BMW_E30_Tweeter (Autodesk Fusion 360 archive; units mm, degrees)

design "Pieza rara - Revised Sizes" references "Pieza rara - slopes edition"
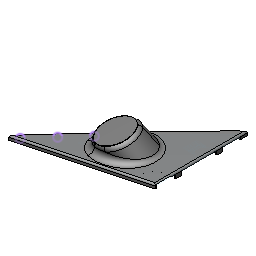
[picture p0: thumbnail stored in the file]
sketch "Sketch1" plane through (0, 0, 0) normal (0, 1, 0) x axis (1, 0, 0)
  line L1 (0, 113) -> (0, 0)
  line L2 (0, 0) -> (0, 113)
  line L3 (-141.545, -37.9726) -> (0, 0)
  point P1 (0, 0)
  point P2 (0, 0)
  point P4 (0, 0)
  point P5 (0, 0)
  point P3 (0, 113)
  point P6 (-141.545, -37.9726)
  vertical L1
  coincident P1 P2
  coincident P1 P4
  coincident P1 P5
  dimension "d1" distance P2 P3 = 113
  dimension "d2" distance P5 P6 = 146.55
sketch "Sketch2" plane through (0, 0, 0) normal (0, 1, 0) x axis (-1, 0, 0)
  curve K1 (0, -113) -> (141.545, 37.9726)
  line L1 (0, 0) -> (0, -113)
  line L2 (141.545, 37.9726) -> (0, 0)
  point P3 (141.545, 37.9726)
  point P5 (141.545, 37.9726)
  point P4 (0, -113)
  point P6 (0, -113)
  point P1 (0, 0)
  point P7 (0, 0)
  point P2 (55.2155, -56.5)
  coincident P3 P5
  coincident P4 P6
  coincident P1 P7
  dimension "d3" distance P1 P2 = 79
extrude "Extrude1" new body sketch "Sketch2" along normal blind 5
shell "Shell1" innerThickness 2
sketch "Sketch3" plane through (0, 3, 0) normal (0, -1, 0) x axis (1, 0, 0)
  line L1 (-2, -1.5342) -> (-2, -108.2224)
  line L2 (-135.5783, 34.3012) -> (-2, -1.5342)
  curve K1 (-2, -108.2224) -> (-135.5783, 34.3012)
  curve K2 (0, -113) -> (-141.545, 37.9726)
  line L3 (-21.3711, -13.7183) -> (-14.6264, -21.1013)
  line L4 (-54.4946, -57.5228) -> (-61.2393, -50.1398)
  line L5 (-41.3052, -31.929) -> (-34.5605, -39.312)
  arc A1 centre (-41.3052, -31.929) radius 27 clockwise from (-61.2393, -50.1398) to (-21.3711, -13.7183)
  arc A2 centre (-34.5605, -39.312) radius 27 clockwise from (-14.6264, -21.1013) to (-54.4946, -57.5228)
  point P7 (-56.867, -51.8313)
  point P15 (-34.5605, -39.312)
  point P17 (-34.5605, -39.312)
  point P16 (-41.3052, -31.929)
  point P18 (-41.3052, -31.929)
  point P9 (-16.9988, -15.4098)
  coincident K1 P7
  tangent L3 A1
  tangent A1 L4
  parallel L3 L4
  tangent L4 A2
  tangent L3 A2
  coincident P15 P17
  coincident P16 P18
  dimension "d7" distance P7 P9 = 54
sketch "Sketch4" plane through (0, 0, 0) normal (0, 0, 1) x axis (1, 0, 0)
  line L1 (-41.3052, 0) -> (-34.5605, 0)
  line L2 (-37.9329, 0) -> (-52.1255, 21.0623)
  circle C1 centre (-52.1255, 21.0623) radius 21.25
  point P2 (-52.1255, 21.0623)
  point P5 (-52.1255, 21.0623)
  point P7 (-52.1255, 21.0623)
  point P9 (-37.9329, 0)
  point P10 (-52.1255, 21.0623)
  point P11 (-37.9329, 0)
  point P12 (-52.1255, 21.0623)
  coincident P2 P5
  coincident P5 P7
  midpoint L1 P9
  coincident P7 P10
  coincident P9 P11
  coincident P5 P12
  dimension "d10" diameter C1 = 42.5
external_derived "ExternalDerived1"
move "Move1"
move "Move2"
move "Move3"
combine "Combine1"
offset_faces "OffsetFaces1" distance 0.066
delete_face "DeleteFace1"
sketch "Sketch5" plane through (0, 3, 0) normal (0, -1, 0) x axis (1, 0, 0)
  curve K1 (-34.855, -41.4726) -> (-64.6786, -43.3994)
  curve K2 (-2.066, -108.0644) -> (-64.6786, -43.3994)
  line L1 (-2.066, -1.5848) -> (-2.066, -108.0644)
  line L2 (-135.3812, 34.18) -> (-2.066, -1.5848)
  curve K3 (-69.9493, -37.7406) -> (-135.3812, 34.18)
  curve K4 (-69.9493, -37.7406) -> (-34.855, -41.4726)
  line L3 (-95.1633, -10.3455) -> (-135.3812, 34.18)
  line L4 (-89.7132, -5.4227) -> (-95.1633, -10.3455)
  line L5 (-93.1705, -1.5951) -> (-89.7132, -5.4227)
  line L6 (-92.5002, -2.3372) -> (-93.1705, -1.5951)
  line L7 (-92.5002, -2.3372) -> (-93.1705, -1.5951)
  line L8 (-88.7898, 1.0143) -> (-92.5002, -2.3372)
  line L9 (-89.4601, 1.7564) -> (-88.7898, 1.0143)
  line L10 (-93.1705, -1.5951) -> (-89.4601, 1.7564)
  line L11 (-91.6863, -0.2545) -> (-93.1705, -1.5951)
  line L12 (-93.0269, 1.2296) -> (-91.6863, -0.2545)
  line L13 (-92.2849, 1.8999) -> (-93.0269, 1.2296)
  line L14 (-90.9443, 0.4158) -> (-92.2849, 1.8999)
  line L15 (-92.2849, 1.8999) -> (-93.0269, 1.2296)
  line L16 (-88.9334, -1.8105) -> (-92.2849, 1.8999)
  line L17 (-89.6754, -2.4808) -> (-88.9334, -1.8105)
  line L18 (-93.0269, 1.2296) -> (-89.6754, -2.4808)
  line L19 (-2.066, -83.0644) -> (-2.066, -108.0644)
  line L20 (-10.066, -83.0644) -> (-2.066, -83.0644)
  line L21 (-10.066, -84.0644) -> (-10.066, -83.0644)
  line L22 (-10.066, -84.0644) -> (-10.066, -83.0644)
  line L23 (-15.066, -84.0644) -> (-10.066, -84.0644)
  line L24 (-15.066, -83.0644) -> (-15.066, -84.0644)
  line L25 (-10.066, -83.0644) -> (-15.066, -83.0644)
  line L26 (-12.066, -83.0644) -> (-10.066, -83.0644)
  line L27 (-12.066, -81.0644) -> (-12.066, -83.0644)
  line L28 (-13.066, -81.0644) -> (-12.066, -81.0644)
  line L29 (-13.066, -86.0644) -> (-13.066, -81.0644)
  line L30 (-12.066, -86.0644) -> (-13.066, -86.0644)
  line L31 (-12.066, -81.0644) -> (-12.066, -86.0644)
  point P6 (-135.3812, 34.18)
  point P8 (-135.3812, 34.18)
  point P9 (-135.3812, 34.18)
  point P10 (-95.1633, -10.3455)
  point P16 (-91.6863, -0.2545)
  point P19 (-90.9443, 0.4158)
  point P4 (-2.066, -108.0644)
  point P22 (-2.066, -108.0644)
  point P23 (-2.066, -108.0644)
  point P24 (-2.066, -83.0644)
  point P12 (-93.1705, -1.5951)
  point P15 (-89.4601, 1.7564)
  point P17 (-93.0269, 1.2296)
  point P18 (-92.2849, 1.8999)
  point P21 (-89.6754, -2.4808)
  point P25 (-10.066, -83.0644)
  point P26 (-10.066, -84.0644)
  point P28 (-15.066, -83.0644)
  point P29 (-12.066, -83.0644)
  point P30 (-12.066, -81.0644)
  point P31 (-13.066, -81.0644)
  point P33 (-12.066, -86.0644)
  coincident P6 P8
  coincident P8 P9
  coincident K3 P10
  perpendicular L3 L4
  perpendicular L4 L5
  perpendicular L4 L6
  perpendicular L7 L8
  parallel L7 L9
  parallel L8 L10
  coincident L10 P16
  perpendicular L11 L12
  perpendicular L12 L13
  coincident L10 P19
  perpendicular L10 L14
  perpendicular L15 L16
  parallel L15 L17
  parallel L16 L18
  coincident P4 P22
  coincident P22 P23
  coincident L1 P24
  perpendicular L19 L20
  perpendicular L20 L21
  perpendicular L22 L23
  parallel L22 L24
  parallel L23 L25
  perpendicular L22 L26
  perpendicular L26 L27
  perpendicular L28 L29
  parallel L28 L30
  parallel L29 L31
  perpendicular L27 L28
  dimension "d24" distance P9 P10 = 60
  dimension "d28" distance P12 P15 = 5
  dimension "d29" distance P12 P16 = 2
  dimension "d30" distance P16 P17 = 2
  dimension "d31" distance P17 P18 = 1
  dimension "d32" distance P17 P21 = 5
  dimension "d41" distance P25 P26 = 1
  dimension "d42" distance P25 P28 = 5
  dimension "d43" distance P25 P29 = 2
  dimension "d44" distance P29 P30 = 2
  dimension "d45" distance P30 P31 = 1
  dimension "d46" distance P30 P33 = 5
extrude "Extrude4" add sketch "Sketch5" profile of L5 L6 L7 L8 L9 L10 L11 L12 L13 L14 L15 L16 L17 L18 along normal blind 12
fillet "Fillet5" radius 2
fillet "Fillet6" radius 7
extrude "Extrude5" add sketch "Sketch5" profile of L21 L22 L23 L24 L25 L26 L27 L28 L29 L30 L31 along normal blind 12
fillet "Fillet7" radius 2
fillet "Fillet8" radius 2
sketch "Sketch6" plane through (0, 0, 0) normal (0, -1, 0) x axis (1, 0, 0)
  line L1 (0, 0) -> (0, -113)
  line L2 (-141.545, 37.9726) -> (0, 0)
  curve K1 (0, -113) -> (-141.545, 37.9726)
  curve K2 (-62.4775, -45.7545) -> (-68.7755, -39.0032)
  curve K3 (-68.7755, -39.0032) -> (-135.3812, 34.18)
  line L3 (-2.066, -1.5848) -> (-135.3812, 34.18)
  line L4 (-2.066, -108.0644) -> (-2.066, -1.5848)
  curve K4 (-2.066, -108.0644) -> (-62.4775, -45.7545)
  line L5 (-138.2134, 34.2442) -> (-141.545, 37.9726)
  line L6 (-134.877, 30.5202) -> (-138.2134, 34.2442)
  curve K5 (-139.1097, 35.2486) -> (-73.8429, -36.5831)
  line L7 (-114.8104, 8.2179) -> (-134.8763, 30.5194)
  line L8 (-113.1141, 6.342) -> (-114.8104, 8.2179)
  line L9 (-134.877, 30.5202) -> (-113.1141, 6.342)
  line L10 (-134.8763, 30.5194) -> (-134.877, 30.5202)
  line L11 (-134.8763, 30.5194) -> (-134.877, 30.5202)
  line L12 (-113.1141, 6.342) -> (-114.8104, 8.2179)
  line L13 (-134.877, 30.5202) -> (-113.1141, 6.342)
  line L14 (-134.877, 30.5202) -> (-134.8763, 30.5194)
  line L15 (-114.8104, 8.2179) -> (-134.8763, 30.5194)
  point P4 (-141.545, 37.9726)
  point P10 (-141.545, 37.9726)
  point P13 (-134.877, 30.5202)
  point P16 (-134.8763, 30.5194)
  point P17 (-114.8104, 8.2179)
  point P18 (-113.1141, 6.342)
  point P12 (-138.2134, 34.2442)
  coincident P4 P10
  coincident K1 P13
  coincident K5 P16
  coincident K5 P17
  coincident K1 P18
  dimension "d57" distance P10 P12 = 5
  dimension "d58" distance P12 P13 = 5
  dimension "d59" distance P16 P17 = 30
split_face "SplitFace1"
split_face "SplitFace2"
delete_face "DeleteFace4"
sketch "Sketch7" plane through (0, 0, 0) normal (0, -1, 0) x axis (1, 0, 0)
  curve K1 (-68.7755, -39.0032) -> (-135.3812, 34.18)
  line L1 (-133.3529, 31.9152) -> (-134.877, 30.5202)
  line L2 (-111.5901, 7.7369) -> (-113.1141, 6.342)
  line L3 (-133.3529, 31.9152) -> (-134.877, 30.5202)
  line L4 (-111.3903, 7.9198) -> (-133.3529, 31.9152)
  line L5 (-112.9143, 6.5249) -> (-111.3903, 7.9198)
  line L6 (-134.877, 30.5202) -> (-112.9143, 6.5249)
  point P2 (-134.877, 30.5202)
  point P5 (-134.877, 30.5202)
  point P6 (-133.3529, 31.9152)
  point P7 (-113.1141, 6.342)
  point P8 (-113.1141, 6.342)
  point P9 (-111.5901, 7.7369)
  point P10 (-134.877, 30.5202)
  coincident P2 P5
  coincident K1 P6
  coincident P7 P8
  coincident K1 P9
  parallel L1 L2
  perpendicular L3 L4
  parallel L3 L5
  parallel L4 L6
  parallel L1 L3
  coincident P2 P10
split_face "SplitFace3"
extrude "Extrude6" cut sketch "Sketch7" profile of K1 L1 L2 L3 L5 L6 against normal blind 3
delete_face "DeleteFace5"
step "RemoveFaces1"
step "RemoveFaces2"
chamfer "Chamfer1" distance 3
sketch "Sketch8" plane through (-52.1255, 21.0623, -25.2438) normal (-0.1729, 0.9763, 0.1303) x axis (0, -0.1323, 0.9912)
  circle C1 centre (2.2976, -2.1686) radius 23.5648
scale "Scale1" ScaleFactor 1.1561
sketch "Sketch9" plane through (0, 0, 0) normal (1, 0, 0) x axis (0, 0, -1)
  line L1 (113, 0) -> (113, 3)
  line L2 (0, 3) -> (113, 3)
  line L3 (0, 0) -> (0, 3)
  line L4 (113, 0) -> (0, 0)
  line L5 (104, 0) -> (113, 0)
  line L6 (104, 3) -> (104, 0)
  line L7 (104, 3) -> (104, 0)
  line L8 (82.89, 3) -> (104, 3)
  line L9 (82.89, 0) -> (82.89, 3)
  line L10 (104, 0) -> (82.89, 0)
  line L11 (82.89, 3) -> (82.89, 0)
  line L12 (75.69, 3) -> (82.89, 3)
  line L13 (75.69, 0) -> (75.69, 3)
  line L14 (82.89, 0) -> (75.69, 0)
  line L15 (75.69, 3) -> (75.69, 0)
  line L16 (32.29, 3) -> (75.69, 3)
  line L17 (32.29, 0) -> (32.29, 3)
  line L18 (75.69, 0) -> (32.29, 0)
  line L19 (32.29, 0) -> (32.29, 3)
  line L20 (25.09, 0) -> (32.29, 0)
  line L21 (25.09, 3) -> (25.09, 0)
  line L22 (32.29, 3) -> (25.09, 3)
  line L23 (25.09, 3) -> (25.09, 0)
  line L24 (0, 3) -> (25.09, 3)
  line L25 (0, 0) -> (0, 3)
  line L26 (25.09, 0) -> (0, 0)
  point P3 (113, 0)
  point P6 (113, 0)
  point P7 (104, 0)
  point P8 (104, 3)
  point P10 (82.89, 0)
  point P12 (75.69, 0)
  point P14 (32.29, 0)
  point P13 (32.29, 3)
  point P16 (25.09, 3)
  coincident P3 P6
  coincident L4 P7
  coincident L2 P8
  perpendicular L2 L6
  perpendicular L7 L8
  parallel L7 L9
  parallel L8 L10
  perpendicular L11 L12
  parallel L11 L13
  parallel L12 L14
  perpendicular L15 L16
  parallel L15 L17
  parallel L16 L18
  perpendicular L19 L20
  parallel L19 L21
  parallel L20 L22
  perpendicular L23 L24
  parallel L23 L25
  parallel L24 L26
  dimension "d67" distance P6 P7 = 9
  dimension "d68" distance P7 P10 = 21.11
  dimension "d69" distance P10 P12 = 7.2
  dimension "d70" distance P12 P14 = 43.4
  dimension "d71" distance P13 P16 = 7.2
sketch "Sketch10" plane through (0, 0, 0) normal (0, -1, 0) x axis (1, 0, 0)
  line L1 (-111.1011, 4.1176) -> (-109.577, 5.5126)
  curve K1 (-111.1011, 4.1176) -> (0, -113)
  line L2 (0, 0) -> (0, -113)
  line L3 (-141.545, 37.9726) -> (0, 0)
  curve K2 (-141.545, 37.9726) -> (-134.877, 30.5202)
  line L4 (-133.3529, 31.9152) -> (-134.877, 30.5202)
  curve K3 (-133.3529, 31.9152) -> (-135.3812, 34.18)
  line L5 (-2.066, -1.5848) -> (-135.3812, 34.18)
  line L6 (-2.066, -108.0644) -> (-2.066, -1.5848)
  curve K4 (-2.066, -108.0644) -> (-109.577, 5.5126)
  line L7 (0, -2.1391) -> (-2.066, -1.5848)
  line L8 (0, 0) -> (0, -25.09)
  line L9 (0, -2.1391) -> (0, -2.1391)
  point P10 (-2.066, -1.5848)
  point P12 (-2.066, -1.5848)
  point P13 (0, -2.1391)
  point P16 (0, -2.1391)
  coincident P10 P12
  coincident L2 P13
  parallel L5 L7
  coincident L8 P16
sketch "Sketch11" plane through (0, 0, 0) normal (1, 0, 0) x axis (0, 0, -1)
  line L1 (25.09, 0) -> (25.09, 3)
  line L2 (2.1391, 0) -> (25.09, 0)
  line L3 (2.1391, 3) -> (2.1391, 0)
  line L4 (25.09, 3) -> (2.1391, 3)
  point P3 (25.09, 0)
  point P7 (25.09, 0)
  point P2 (25.09, 3)
  point P6 (25.09, 3)
  perpendicular L1 L2
  parallel L1 L3
  parallel L2 L4
  coincident P3 P7
  coincident P2 P6
extrude "Extrude7" cut sketch "Sketch9" profile of L2 L4 L13 L15 L16 L17 L18 L19 against normal blind 4
extrude "Extrude8" cut sketch "Sketch9" profile of L2 L4 L6 L7 L8 L9 L10 L11 against normal blind 4
extrude "Extrude9" cut sketch "Sketch11" against normal blind 3
delete_face "DeleteFace6"
chamfer "Chamfer2" distance 0.8 distance 3
chamfer "Chamfer3" distance 0.8 distance 3
chamfer "Chamfer4" distance 0.8 distance 3
extrude "Extrude10" add of existing geometry blind 2
sketch "Sketch12" plane through (-0.5353, 0, -1.9954) normal (-0.2591, 0, -0.9658) x axis (-0.9658, 0, 0.2591)
  line L1 (-0.5543, 3) -> (139.614, 3)
  line L2 (-0.5543, 0) -> (-0.5543, 3)
  line L3 (139.614, 0) -> (-0.5543, 0)
  line L4 (139.614, 0) -> (139.614, 3)
sketch "Sketch13" plane through (-0.5353, 0, -1.9954) normal (-0.2591, 0, -0.9658) x axis (-0.9658, 0, 0.2591)
  line L1 (-0.5543, 3) -> (139.614, 3)
  line L2 (-0.5543, 0) -> (-0.5543, 3)
  line L3 (139.614, 0) -> (-0.5543, 0)
  line L4 (139.614, 0) -> (139.614, 3)
  line L5 (78.3765, 3) -> (78.3765, 0)
  line L6 (75.3765, 3) -> (78.3765, 3)
  line L7 (75.3765, 0) -> (75.3765, 3)
  line L8 (78.3765, 0) -> (75.3765, 0)
  line L9 (75.3765, 3) -> (78.3765, 3)
  line L10 (75.3765, 1) -> (75.3765, 3)
  line L11 (78.3765, 1) -> (75.3765, 1)
  line L12 (78.3765, 3) -> (78.3765, 1)
  point P7 (78.3765, 3)
  point P6 (78.3765, 0)
  point P9 (75.3765, 0)
  point P11 (78.3765, 1)
  perpendicular L5 L6
  parallel L5 L7
  parallel L6 L8
  coincident L1 P7
  perpendicular L1 L5
  coincident L3 P6
  perpendicular L9 L10
  parallel L9 L11
  parallel L10 L12
  dimension "d86" distance P6 P9 = 3
  dimension "d87" distance P7 P11 = 2
extrude "Extrude11" add sketch "Sketch13" profile of L1 L5 L6 L7 L9 L10 L11 L12 along normal blind 41.5
offset_faces "OffsetFaces5" distance -1
sketch "Sketch14" plane through (0, 3, 0) normal (0, -1, 0) x axis (1, 0, 0)
  line L1 (-76.8828, 4.3204) -> (-73.3376, 17.5354)
  curve K1 (-76.8828, 4.3204) -> (-62.2677, 9.2949)
  curve K2 (-62.2677, 9.2949) -> (-56.8017, -51.8044)
  curve K3 (-2.066, -108.0644) -> (-56.8017, -51.8044)
  line L2 (-2.066, -104) -> (-2.066, -108.0644)
  line L3 (0, -104) -> (-2.066, -104)
  line L4 (0, -82.89) -> (0, -104)
  line L5 (-2.066, -82.89) -> (0, -82.89)
  line L6 (-2.066, -75.69) -> (-2.066, -82.89)
  line L7 (0, -75.69) -> (-2.066, -75.69)
  line L8 (0, -32.29) -> (0, -75.69)
  line L9 (-2.066, -32.29) -> (0, -32.29)
  line L10 (-2.066, -25.09) -> (-2.066, -32.29)
  line L11 (0, -25.09) -> (-2.066, -25.09)
  line L12 (0, -2.1391) -> (0, -25.09)
  line L13 (-73.3376, 17.5354) -> (0, -2.1391)
  line L14 (-15.066, -84.0644) -> (-13.066, -84.0644)
  line L15 (-15.066, -83.0644) -> (-15.066, -84.0644)
  line L16 (-13.066, -83.0644) -> (-15.066, -83.0644)
  line L17 (-13.066, -81.0644) -> (-13.066, -83.0644)
  line L18 (-12.066, -81.0644) -> (-13.066, -81.0644)
  line L19 (-12.066, -83.0644) -> (-12.066, -81.0644)
  line L20 (-10.066, -83.0644) -> (-12.066, -83.0644)
  line L21 (-10.066, -84.0644) -> (-10.066, -83.0644)
  line L22 (-12.066, -84.0644) -> (-10.066, -84.0644)
  line L23 (-12.066, -86.0644) -> (-12.066, -84.0644)
  line L24 (-13.066, -86.0644) -> (-12.066, -86.0644)
  line L25 (-13.066, -84.0644) -> (-13.066, -86.0644)
sketch "Sketch15" plane through (0, 0, 0) normal (0, 1, 0) x axis (1, 0, 0)
  line L1 (0.2646, -423.3333) -> (0.2646, -211.799)
  line L2 (135.0698, -423.3333) -> (0.2646, -423.3333)
  line L3 (269.875, -423.3333) -> (135.0698, -423.3333)
  line L4 (269.875, -211.799) -> (269.875, -423.3333)
  line L5 (269.875, -0.2646) -> (269.875, -211.799)
  line L6 (135.0698, -0.2646) -> (269.875, -0.2646)
  line L7 (0.2646, -0.2646) -> (135.0698, -0.2646)
  line L8 (0.2646, -211.799) -> (0.2646, -0.2646)
  line L9 (76.7292, -29.6333) -> (76.7292, -19.7115)
  line L10 (67.601, -29.6333) -> (76.7292, -29.6333)
  line L11 (58.4729, -29.6333) -> (67.601, -29.6333)
  line L12 (58.4729, -24.8708) -> (58.4729, -29.6333)
  line L13 (58.4729, -20.1083) -> (58.4729, -24.8708)
  line L14 (52.2552, -20.1083) -> (58.4729, -20.1083)
  line L15 (46.0375, -20.1083) -> (52.2552, -20.1083)
  line L16 (46.0375, -32.9406) -> (46.0375, -20.1083)
  line L17 (46.0375, -45.7729) -> (46.0375, -32.9406)
  line L18 (50.7471, -45.72) -> (46.0375, -45.7729)
  line L19 (55.4302, -45.6406) -> (50.7471, -45.72)
  line L20 (55.5096, -43.5769) -> (55.4302, -45.6406)
  line L21 (55.589, -41.5396) -> (55.5096, -43.5769)
  line L22 (61.9919, -41.5925) -> (55.589, -41.5396)
  line L23 (68.3948, -41.6719) -> (61.9919, -41.5925)
  line L24 (68.3948, -51.1969) -> (68.3948, -41.6719)
  line L25 (68.3948, -60.7219) -> (68.3948, -51.1969)
  line L26 (61.9919, -60.8012) -> (68.3948, -60.7219)
  line L27 (55.5625, -60.8542) -> (61.9919, -60.8012)
  line L28 (55.536, -60.2721) -> (55.5625, -60.8542)
  curve K1 (55.4831, -58.2083) -> (55.536, -60.2721)
  line L29 (55.4302, -56.7531) -> (55.4831, -58.2083)
  line L30 (50.7206, -56.6737) -> (55.4302, -56.7531)
  line L31 (46.0375, -56.6208) -> (50.7206, -56.6737)
  line L32 (46.0904, -70.829) -> (46.0375, -56.6208)
  line L33 (46.1698, -85.0635) -> (46.0904, -70.829)
  line L34 (52.2552, -85.0635) -> (46.1698, -85.0635)
  line L35 (58.3406, -85.0635) -> (52.2552, -85.0635)
  line L36 (58.42, -78.7665) -> (58.3406, -85.0635)
  line L37 (58.4729, -72.4958) -> (58.42, -78.7665)
  line L38 (67.3365, -72.4958) -> (58.4729, -72.4958)
  line L39 (76.2, -72.4958) -> (67.3365, -72.4958)
  line L40 (76.2, -83.8465) -> (76.2, -72.4958)
  curve K2 (75.8031, -95.3558) -> (76.2, -83.8465)
  curve K3 (16.0337, -95.3558) -> (75.8031, -95.3558)
  curve K4 (15.6104, -91.784) -> (16.0337, -95.3558)
  line L41 (15.6104, -88.3708) -> (15.6104, -91.784)
  line L42 (16.9333, -87.5242) -> (15.6104, -88.3708)
  line L43 (18.2563, -86.651) -> (16.9333, -87.5242)
  line L44 (18.2563, -52.6521) -> (18.2563, -86.651)
  line L45 (18.2563, -18.6531) -> (18.2563, -52.6521)
  line L46 (16.9333, -17.7271) -> (18.2563, -18.6531)
  line L47 (15.6369, -16.801) -> (16.9333, -17.7271)
  line L48 (15.6104, -13.4673) -> (15.6369, -16.801)
  curve K5 (15.7956, -9.9748) -> (15.6104, -13.4673)
  curve K6 (46.355, -9.7896) -> (15.7956, -9.9748)
  line L49 (76.7292, -9.7896) -> (46.355, -9.7896)
  line L50 (76.7292, -19.7115) -> (76.7292, -9.7896)
  curve K7 (128.9844, -29.2365) -> (124.2748, -16.0073)
  curve K8 (133.0325, -40.5606) -> (128.9844, -29.2365)
  curve K9 (134.8052, -44.3706) -> (133.0325, -40.5606)
  curve K10 (141.4198, -26.8817) -> (134.8052, -44.3706)
  line L51 (147.7698, -9.7896) -> (141.4198, -26.8817)
  line L52 (165.1529, -9.7896) -> (147.7698, -9.7896)
  line L53 (182.5625, -9.7896) -> (165.1529, -9.7896)
  line L54 (182.5625, -13.2821) -> (182.5625, -9.7896)
  line L55 (182.536, -16.801) -> (182.5625, -13.2821)
  line L56 (181.2396, -17.8065) -> (182.536, -16.801)
  line L57 (179.9167, -18.8119) -> (181.2396, -17.8065)
  line L58 (179.9431, -52.7315) -> (179.9167, -18.8119)
  line L59 (179.9431, -86.651) -> (179.9431, -52.7315)
  line L60 (181.1867, -87.4712) -> (179.9431, -86.651)
  line L61 (182.4302, -88.2915) -> (181.1867, -87.4712)
  line L62 (182.4302, -91.8369) -> (182.4302, -88.2915)
  line L63 (182.4302, -95.3823) -> (182.4302, -91.8369)
  line L64 (166.5552, -95.4617) -> (182.4302, -95.3823)
  curve K11 (150.0981, -95.3823) -> (166.5552, -95.4617)
  curve K12 (149.4896, -91.9956) -> (150.0981, -95.3823)
  curve K13 (149.7013, -88.4767) -> (149.4896, -91.9956)
  curve K14 (150.9448, -87.4448) -> (149.7013, -88.4767)
  curve K15 (152.1883, -86.3865) -> (150.9448, -87.4448)
  curve K16 (152.1619, -38.8938) -> (152.1883, -86.3865)
  curve K17 (151.6592, -39.8727) -> (152.1619, -38.8938)
  curve K18 (146.976, -54.901) -> (151.6592, -39.8727)
  curve K19 (141.8167, -71.3052) -> (146.976, -54.901)
  curve K20 (139.8852, -77.5229) -> (141.8167, -71.3052)
  curve K21 (137.0013, -86.651) -> (139.8852, -77.5229)
  line L65 (135.3344, -91.9427) -> (137.0013, -86.651)
  line L66 (130.175, -91.9427) -> (135.3344, -91.9427)
  line L67 (125.0421, -91.9427) -> (130.175, -91.9427)
  line L68 (123.534, -87.0479) -> (125.0421, -91.9427)
  curve K22 (118.7979, -71.3052) -> (123.534, -87.0479)
  curve K23 (109.2729, -39.4229) -> (118.7979, -71.3052)
  curve K24 (109.0348, -62.7592) -> (109.2729, -39.4229)
  curve K25 (109.4846, -86.8892) -> (109.0348, -62.7592)
  curve K26 (110.8075, -87.8417) -> (109.4846, -86.8892)
  line L69 (111.6542, -88.6619) -> (110.8075, -87.8417)
  line L70 (111.6542, -91.9427) -> (111.6542, -88.6619)
  curve K27 (111.0721, -95.3823) -> (111.6542, -91.9427)
  curve K28 (98.9542, -95.4617) -> (111.0721, -95.3823)
  line L71 (87.4448, -95.3823) -> (98.9542, -95.4617)
  line L72 (87.3654, -91.8104) -> (87.4448, -95.3823)
  line L73 (87.3125, -88.2385) -> (87.3654, -91.8104)
  line L74 (88.6354, -87.339) -> (87.3125, -88.2385)
  line L75 (89.9583, -86.4394) -> (88.6354, -87.339)
  line L76 (89.9583, -52.6256) -> (89.9583, -86.4394)
  line L77 (89.9583, -18.8383) -> (89.9583, -52.6256)
  line L78 (88.6354, -17.8594) -> (89.9583, -18.8383)
  line L79 (87.3125, -16.8804) -> (88.6354, -17.8594)
  line L80 (87.3125, -13.335) -> (87.3125, -16.8804)
  line L81 (87.3125, -9.7896) -> (87.3125, -13.335)
  line L82 (104.7221, -9.8425) -> (87.3125, -9.7896)
  line L83 (122.1052, -9.9219) -> (104.7221, -9.8425)
  line L84 (124.2748, -16.0073) -> (122.1052, -9.9219)
  curve K29 (253.5238, -19.8173) -> (253.4973, -9.8954)
  line L85 (253.4708, -29.6333) -> (253.5238, -19.8173)
  line L86 (244.3427, -29.6333) -> (253.4708, -29.6333)
  line L87 (235.2146, -29.6333) -> (244.3427, -29.6333)
  line L88 (235.2146, -24.8708) -> (235.2146, -29.6333)
  line L89 (235.2146, -20.1083) -> (235.2146, -24.8708)
  line L90 (228.9969, -20.1083) -> (235.2146, -20.1083)
  line L91 (222.7792, -20.1083) -> (228.9969, -20.1083)
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extrude "Extrude12" new body sketch "Sketch15" along normal blind 1
move "Move4"
move "Move5"
scale "Scale2" ScaleFactor 0.07
combine "Combine2"
move "Move6"
move "Move7"
extrude "Extrude13" add of existing geometry blind 1
combine "Combine3"
surface_patch "SurfacePatch1"
extrude "Extrude14" cut of existing geometry blind 1
hole "Hole1" HoleDepth 0.5 HoleDiameter 1 TipAngle 118
surface_delete_face "SurfaceDeleteFace1"
extrude "Extrude16" new body of existing geometry blind 1
combine "Combine4"
delete_face "DeleteFace7"
extrude "Extrude17" cut of existing geometry blind -1
fillet "Fillet10" radius 9.3
sketch "Sketch16" plane through (0, 3, 0) normal (0, -1, 0) x axis (1, 0, 0)
  curve K1 (-16.8138, -63.2665) -> (-16.8256, -63.5816)
  curve K2 (-16.4855, -62.5688) -> (-16.8138, -63.2665)
  curve K3 (-15.4754, -62.3625) -> (-16.4855, -62.5688)
  curve K4 (-14.2686, -62.4238) -> (-15.4754, -62.3625)
  curve K5 (-13.6231, -63.3345) -> (-14.2686, -62.4238)
  curve K6 (-13.9382, -64.534) -> (-13.6231, -63.3345)
  curve K7 (-15.2079, -64.7183) -> (-13.9382, -64.534)
  curve K8 (-16.4703, -64.5338) -> (-15.2079, -64.7183)
  curve K9 (-16.8256, -63.5816) -> (-16.4703, -64.5338)
  curve K10 (-16.7805, -60.232) -> (-16.8028, -61.1955)
  curve K11 (-16.2278, -59.6715) -> (-16.7805, -60.232)
  curve K12 (-15.2774, -59.6848) -> (-16.2278, -59.6715)
  curve K13 (-14.7985, -59.9924) -> (-15.2774, -59.6848)
  curve K14 (-14.7277, -60.0154) -> (-14.7985, -59.9924)
  curve K15 (-14.5393, -59.7421) -> (-14.7277, -60.0154)
  curve K16 (-13.8218, -59.6607) -> (-14.5393, -59.7421)
  line L1 (-13.3476, -59.6627) -> (-13.8218, -59.6607)
  line L2 (-13.2965, -59.6119) -> (-13.3476, -59.6627)
  curve K17 (-13.099, -59.5645) -> (-13.2965, -59.6119)
  line L3 (-12.9527, -59.5678) -> (-13.099, -59.5645)
  line L4 (-12.9437, -59.7899) -> (-12.9527, -59.5678)
  curve K18 (-13.0198, -60.5061) -> (-12.9437, -59.7899)
  line L5 (-13.0516, -60.6066) -> (-13.0198, -60.5061)
  line L6 (-13.7535, -60.6173) -> (-13.0516, -60.6066)
  curve K19 (-14.5104, -60.6604) -> (-13.7535, -60.6173)
  curve K20 (-14.6817, -60.8445) -> (-14.5104, -60.6604)
  curve K21 (-14.1815, -60.9739) -> (-14.6817, -60.8445)
  line L7 (-13.6443, -60.9787) -> (-14.1815, -60.9739)
  line L8 (-13.5764, -60.9314) -> (-13.6443, -60.9787)
  curve K22 (-13.3735, -60.8801) -> (-13.5764, -60.9314)
  curve K23 (-13.2381, -60.8928) -> (-13.3735, -60.8801)
  curve K24 (-13.3291, -61.1202) -> (-13.2381, -60.8928)
  curve K25 (-13.6017, -61.9431) -> (-13.3291, -61.1202)
  line L9 (-13.6136, -62.0137) -> (-13.6017, -61.9431)
  line L10 (-13.7451, -62.0157) -> (-13.6136, -62.0137)
  curve K26 (-13.9162, -61.9701) -> (-13.7451, -62.0157)
  line L11 (-13.954, -61.9244) -> (-13.9162, -61.9701)
  line L12 (-15.2134, -61.9325) -> (-13.954, -61.9244)
  line L13 (-16.4747, -61.9407) -> (-15.2134, -61.9325)
  line L14 (-16.5054, -61.9893) -> (-16.4747, -61.9407)
  curve K27 (-16.6676, -62.0418) -> (-16.5054, -61.9893)
  line L15 (-16.7991, -62.0438) -> (-16.6676, -62.0418)
  line L16 (-16.8028, -61.1955) -> (-16.7991, -62.0438)
  line L17 (-16.511, -72.5438) -> (-16.6162, -72.5676)
  curve K28 (-15.9426, -72.4036) -> (-16.511, -72.5438)
  curve K29 (-15.1398, -72.208) -> (-15.9426, -72.4036)
  curve K30 (-14.7708, -72.1134) -> (-15.1398, -72.208)
  curve K31 (-15.087, -72.0275) -> (-14.7708, -72.1134)
  curve K32 (-16.4214, -71.7348) -> (-15.087, -72.0275)
  line L18 (-16.6296, -71.688) -> (-16.4214, -71.7348)
  line L19 (-16.6479, -70.488) -> (-16.6296, -71.688)
  line L20 (-16.4646, -70.4852) -> (-16.6479, -70.488)
  curve K33 (-16.2269, -70.526) -> (-16.4646, -70.4852)
  line L21 (-16.1744, -70.5678) -> (-16.2269, -70.526)
  line L22 (-14.989, -70.5608) -> (-16.1744, -70.5678)
  curve K34 (-13.17, -70.5645) -> (-14.989, -70.5608)
  line L23 (-12.5364, -70.5752) -> (-13.17, -70.5645)
  line L24 (-12.4741, -70.528) -> (-12.5364, -70.5752)
  curve K35 (-12.2915, -70.477) -> (-12.4741, -70.528)
  curve K36 (-12.1117, -70.4854) -> (-12.2915, -70.477)
  line L25 (-12.0541, -70.4956) -> (-12.1117, -70.4854)
  line L26 (-12.0368, -71.6271) -> (-12.0541, -70.4956)
  line L27 (-12.2222, -71.6207) -> (-12.0368, -71.6271)
  curve K37 (-12.4601, -71.5687) -> (-12.2222, -71.6207)
  line L28 (-12.5108, -71.5213) -> (-12.4601, -71.5687)
  line L29 (-13.3537, -71.5138) -> (-12.5108, -71.5213)
  curve K38 (-14.6227, -71.5054) -> (-13.3537, -71.5138)
  curve K39 (-14.4726, -71.631) -> (-14.6227, -71.5054)
  curve K40 (-13.6735, -71.7966) -> (-14.4726, -71.631)
  curve K41 (-12.8745, -71.9659) -> (-13.6735, -71.7966)
  curve K42 (-12.3318, -72.0799) -> (-12.8745, -71.9659)
  line L30 (-12.1962, -72.1093) -> (-12.3318, -72.0799)
  line L31 (-12.1935, -72.2834) -> (-12.1962, -72.1093)
  curve K43 (-12.2333, -72.4673) -> (-12.1935, -72.2834)
  curve K44 (-12.7265, -72.5582) -> (-12.2333, -72.4673)
  curve K45 (-13.3452, -72.677) -> (-12.7265, -72.5582)
  curve K46 (-13.7697, -72.7761) -> (-13.3452, -72.677)
  curve K47 (-14.3974, -72.9153) -> (-13.7697, -72.7761)
  line L32 (-14.7666, -72.9932) -> (-14.3974, -72.9153)
  line L33 (-14.424, -72.9898) -> (-14.7666, -72.9932)
  curve K48 (-12.9457, -72.9987) -> (-14.424, -72.9898)
  line L34 (-11.8101, -73.011) -> (-12.9457, -72.9987)
  line L35 (-11.7368, -72.9599) -> (-11.8101, -73.011)
  curve K49 (-11.4522, -72.9185) -> (-11.7368, -72.9599)
  line L36 (-11.239, -72.9282) -> (-11.4522, -72.9185)
  line L37 (-11.2365, -73.3375) -> (-11.239, -72.9282)
  line L38 (-11.2357, -73.7487) -> (-11.2365, -73.3375)
  line L39 (-11.4505, -73.752) -> (-11.2357, -73.7487)
  curve K50 (-11.7383, -73.7082) -> (-11.4505, -73.752)
  line L40 (-11.8113, -73.6593) -> (-11.7383, -73.7082)
  line L41 (-12.5802, -73.6488) -> (-11.8113, -73.6593)
  curve K51 (-14.6862, -73.6495) -> (-12.5802, -73.6488)
  line L42 (-16.0253, -73.6607) -> (-14.6862, -73.6495)
  line L43 (-16.0875, -73.7098) -> (-16.0253, -73.6607)
  curve K52 (-16.3645, -73.7622) -> (-16.0875, -73.7098)
  line L44 (-16.5794, -73.7655) -> (-16.3645, -73.7622)
  line L45 (-16.5914, -73.3434) -> (-16.5794, -73.7655)
  curve K53 (-16.6098, -72.7453) -> (-16.5914, -73.3434)
  line L46 (-16.6162, -72.5676) -> (-16.6098, -72.7453)
  curve K54 (-16.8847, -58.0201) -> (-16.8935, -58.5351)
  curve K55 (-16.7466, -57.7197) -> (-16.8847, -58.0201)
  curve K56 (-16.7701, -57.6349) -> (-16.7466, -57.7197)
  line L47 (-16.826, -57.6135) -> (-16.7701, -57.6349)
  line L48 (-16.8297, -57.3765) -> (-16.826, -57.6135)
  curve K57 (-16.8038, -57.1279) -> (-16.8297, -57.3765)
  curve K58 (-15.8966, -57.1029) -> (-16.8038, -57.1279)
  curve K59 (-15.0184, -57.1117) -> (-15.8966, -57.1029)
  curve K60 (-15.0108, -57.4876) -> (-15.0184, -57.1117)
  line L49 (-15.0036, -57.8394) -> (-15.0108, -57.4876)
  line L50 (-15.409, -57.8586) -> (-15.0036, -57.8394)
  curve K61 (-16.0321, -57.9292) -> (-15.409, -57.8586)
  curve K62 (-16.1326, -58.1438) -> (-16.0321, -57.9292)
  curve K63 (-16.0349, -58.3535) -> (-16.1326, -58.1438)
  curve K64 (-14.7794, -58.3287) -> (-16.0349, -58.3535)
  curve K65 (-14.6368, -58.2061) -> (-14.7794, -58.3287)
  curve K66 (-14.356, -57.6721) -> (-14.6368, -58.2061)
  curve K67 (-13.6063, -57.0346) -> (-14.356, -57.6721)
  curve K68 (-12.2989, -57.0165) -> (-13.6063, -57.0346)
  curve K69 (-11.601, -57.4726) -> (-12.2989, -57.0165)
  curve K70 (-11.4945, -58.0174) -> (-11.601, -57.4726)
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form "Form1"
sketch "Sketch17" plane through (0, 3, 0) normal (0, -1, 0) x axis (1, 0, 0)
  line L1 (0, -25.09) -> (0, -2.1391)
  line L2 (0, -2.1391) -> (0, -20)
  line L3 (-14.5, -15) -> (0, -20)
  line L4 (-23.0522, 4.0452) -> (-14.5, -15)
  line L5 (0, -2.1391) -> (-23.0522, 4.0452)
  point P5 (0, -20)
  point P4 (0, -2.1391)
  point P6 (0, -2.1391)
  point P7 (-14.5, -15)
  point P8 (-14.5, -15)
  point P9 (-23.0522, 4.0452)
  point P10 (-23.0522, 4.0452)
  point P11 (0, -2.1391)
  point P12 (0, -2.1391)
  coincident L1 P5
  coincident P4 P6
  coincident P7 P8
  coincident P9 P10
  coincident P11 P12
extrude "Extrude18" cut sketch "Sketch17" against normal blind 1
fillet "Fillet11" radius 15
extrude "Extrude19" add of existing geometry blind 0.5 second side blind 0
extrude "Extrude20" add of existing geometry blind 0.5
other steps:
derived_base_feature "Derived Base Feature" bodies "Body1 (1)"
named bodies: "Body1 (1)"

design "Pieza rara - slopes edition"
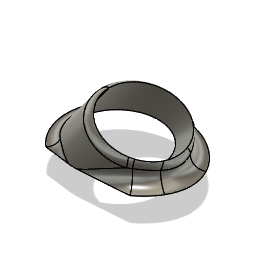
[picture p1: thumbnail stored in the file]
sketch "Sketch1" plane through (0, 0, 0) normal (0, 1, 0) x axis (1, 0, 0)
  line L1 (-205, 0) -> (0, 0)
  line L2 (-125.0969, 79.9031) -> (-205, 0)
  line L3 (0, 0) -> (-125.0969, 79.9031)
  point P1 (0, 0)
  point P2 (0, 0)
  point P5 (0, 0)
  point P3 (-205, 0)
  point P4 (-125.0969, 79.9031)
  coincident P1 P2
  horizontal L1
  coincident P1 P5
  dimension "d1" distance P2 P3 = 205
  dimension "d2" angle L1 L2 = 45
  dimension "d3" distance P3 P4 = 113
extrude "Extrude1" new body sketch "Sketch1" along normal blind 5
sketch "Sketch2" plane through (0, 5, 0) normal (0, 1, 0) x axis (-1, 0, 0)
  line L1 (205, 0) -> (125.0969, -79.9031)
  line L2 (0, 0) -> (205, 0)
  line L3 (125.0969, -79.9031) -> (0, 0)
  line L4 (205, 0) -> (0, 0)
  line L5 (125, 0) -> (205, 0)
  circle C1 centre (125, -25) radius 25
  circle C2 centre (105, -25) radius 20
  point P5 (205, 0)
  point P8 (205, 0)
  point P9 (125, 0)
  coincident P5 P8
  coincident L4 P9
  coincident P9 C1
shell "Shell1" innerThickness 2
sketch "Sketch3" plane through (0, 0, 0) normal (0, 0, 1) x axis (1, 0, 0)
  line L1 (0, 0) -> (-205, 0)
  line L2 (0, 5) -> (0, 0)
  line L3 (-205, 5) -> (0, 5)
  line L4 (-205, 0) -> (-205, 5)
  line L5 (-124.9995, 30) -> (-85.0095, 15)
  line L6 (-155, 5) -> (-125, 5)
  line L7 (-125, 0) -> (-105.0045, 22.5)
  circle C1 centre (-105, 5) radius 20
  circle C2 centre (-106.1526, 22.6955) radius 22.5
  point P6 (-124.9995, 5)
  point P9 (-85.0095, 5)
  point P12 (-85.0095, 15)
  point P13 (-85.0095, 15)
  point P8 (-124.9995, 30)
  point P14 (-124.9995, 30)
  point P15 (-125, 5)
  point P16 (-125, 5)
  point P17 (-155, 5)
  point P18 (-105.0045, 22.5)
  point P20 (-105.0045, 22.5)
  point P19 (-125, 0)
  point P21 (-125, 0)
  point P11 (-85.0095, 15)
  coincident P6 C1
  coincident C1 P9
  coincident P12 P13
  coincident P8 P14
  coincident L3 P15
  coincident P15 P16
  coincident L3 P17
  parallel L3 L6
  midpoint L5 P18
  coincident P18 P20
  coincident P19 P21
  coincident P11 C2
  dimension "d11" diameter C2 = 45
loft "Loft1" sketch "Sketch2" + "Sketch3"
split "Split1"
remove_body "RemoveBody1"
shell "Shell2" innerThickness 2
extrude "Extrude2" cut of existing geometry blind -15
combine "Combine1"
fillet "Fillet1" radius 2.5
offset_faces "OffsetFaces1" distance -1
fillet "Fillet2" radius 6.5
fillet "Fillet3" radius 1.5
sketch "Sketch10" plane through (0, 5, 0) normal (0, 1, 0) x axis (-1, 0, 0)
sketch "Sketch5" plane through (0, 3, 0) normal (0, -1, 0) x axis (1, 0, 0)
  curve K1 (-118.8855, -1) -> (-145.2681, -24.8743)
  curve K2 (-145.2681, -24.8743) -> (-122.8387, -1)
  line L1 (-202.5858, -1) -> (-122.8387, -1)
  line L2 (-124.958, -78.6278) -> (-202.5858, -1)
  line L3 (-3.4233, -1) -> (-124.958, -78.6278)
  line L4 (-118.8855, -1) -> (-3.4233, -1)
  line L5 (-63.4233, -1) -> (-3.4233, -1)
  line L6 (-63.4233, -11) -> (-63.4233, -1)
  line L7 (-62.9233, -11) -> (-63.9233, -11)
  line L8 (-63.9233, -16) -> (-63.9233, -11)
  line L9 (-62.9233, -16) -> (-63.9233, -16)
  line L10 (-62.9233, -11) -> (-62.9233, -16)
  line L11 (-63.9233, -13) -> (-63.9233, -11)
  line L12 (-65.9233, -14) -> (-65.9233, -13)
  line L13 (-60.9233, -14) -> (-65.9233, -14)
  line L14 (-60.9233, -13) -> (-60.9233, -14)
  line L15 (-65.9233, -13) -> (-60.9233, -13)
  point P7 (-3.4233, -1)
  point P8 (-3.4233, -1)
  point P9 (-63.4233, -1)
  coincident P7 P8
  parallel L4 L5
  perpendicular L5 L6
  dimension "d19" distance P8 P9 = 60
extrude "Extrude3" add sketch "Sketch5" profile of L7 L8 L9 L10 L11 L12 L13 L14 L15 along normal blind 5
sketch "Sketch6" plane through (0, 3, 0) normal (0, -1, 0) x axis (1, 0, 0)
  line L1 (-62.9233, -11) -> (-63.9233, -11)
  line L2 (-62.9233, -13) -> (-62.9233, -11)
  line L3 (-60.9233, -13) -> (-62.9233, -13)
  line L4 (-60.9233, -14) -> (-60.9233, -13)
  line L5 (-62.9233, -14) -> (-60.9233, -14)
  line L6 (-62.9233, -16) -> (-62.9233, -14)
  line L7 (-63.9233, -16) -> (-62.9233, -16)
  line L8 (-63.9233, -14) -> (-63.9233, -16)
  line L9 (-65.9233, -14) -> (-63.9233, -14)
  line L10 (-65.9233, -13) -> (-65.9233, -14)
  line L11 (-63.9233, -13) -> (-65.9233, -13)
  line L12 (-63.9233, -11) -> (-63.9233, -13)
  curve K1 (-118.8855, -1) -> (-145.2681, -24.8743)
  curve K2 (-145.2681, -24.8743) -> (-122.8387, -1)
  line L13 (-202.5858, -1) -> (-122.8387, -1)
  line L14 (-124.958, -78.6278) -> (-202.5858, -1)
  line L15 (-3.4233, -1) -> (-124.958, -78.6278)
  line L16 (-118.8855, -1) -> (-3.4233, -1)
  line L17 (-184.9081, -18.6777) -> (-202.5858, -1)
  line L18 (-179.2513, -13.0208) -> (-184.9081, -18.6777)
  line L19 (-179.9584, -12.3137) -> (-179.2513, -13.0208)
  line L20 (-176.4228, -8.7782) -> (-179.9584, -12.3137)
  line L21 (-175.7157, -9.4853) -> (-176.4228, -8.7782)
  line L22 (-179.2513, -13.0208) -> (-175.7157, -9.4853)
  line L23 (-177.837, -11.6066) -> (-179.2513, -13.0208)
  line L24 (-176.4228, -13.0208) -> (-177.837, -11.6066)
  line L25 (-175.7157, -12.3137) -> (-176.4228, -13.0208)
  line L26 (-179.2513, -8.7782) -> (-175.7157, -12.3137)
  line L27 (-179.9584, -9.4853) -> (-179.2513, -8.7782)
  line L28 (-176.4228, -13.0208) -> (-179.9584, -9.4853)
  point P17 (-202.5858, -1)
  point P20 (-202.5858, -1)
  point P21 (-184.9081, -18.6777)
  point P26 (-177.837, -11.6066)
  coincident P17 P20
  coincident L14 P21
  perpendicular L17 L18
  perpendicular L18 L19
  perpendicular L17 L20
  perpendicular L20 L21
  perpendicular L19 L22
  coincident L22 P26
  perpendicular L19 L23
  perpendicular L22 L24
  perpendicular L24 L25
  perpendicular L25 L26
  perpendicular L26 L27
  perpendicular L25 L28
extrude "Extrude4" add sketch "Sketch6" profile of L19 L20 L21 L22 L23 L24 L25 L26 L27 L28 along normal blind 5
sketch "Sketch7" plane through (0, 0, 0) normal (0, 0, 1) x axis (1, 0, 0)
  line L1 (-205, 2.5) -> (0, 2.5)
  line L2 (-205, 0) -> (-205, 2.5)
  line L3 (0, 0) -> (-205, 0)
  line L4 (0, 2.5) -> (0, 0)
  line L5 (-40, 0) -> (-205, 0)
  line L6 (-3, 0) -> (0, 0)
  line L7 (-5, 2.5) -> (0, 2.5)
  line L8 (-35, 2.5) -> (0, 2.5)
  line L9 (-40, 0) -> (-35, 2.5)
  line L10 (-5, 2.5) -> (-3, 0)
  line L11 (0, 2.5) -> (0, 0)
  point P4 (-205, 0)
  point P6 (-205, 0)
  point P5 (0, 0)
  point P8 (0, 0)
  point P2 (0, 2.5)
  point P10 (0, 2.5)
  point P11 (-5, 2.5)
  point P12 (0, 2.5)
  point P13 (-35, 2.5)
  point P7 (-40, 0)
  point P9 (-3, 0)
  coincident P4 P6
  perpendicular L2 L5
  coincident P5 P8
  perpendicular L4 L6
  coincident P2 P10
  coincident L1 P11
  perpendicular L4 L7
  coincident P2 P12
  coincident L1 P13
  perpendicular L4 L8
  dimension "d34" distance P6 P7 = 165
  dimension "d35" distance P8 P9 = 3
extrude "Extrude5" cut sketch "Sketch7" profile of L1 L3 L8 L9 L10 against normal blind 1
sketch "Sketch9" plane through (-102.5, 0, -102.5) normal (-0.7071, 0, -0.7071) x axis (-0.7071, 0, 0.7071)
  line L1 (31.9569, 2.5) -> (144.9569, 2.5)
  line L2 (31.9569, 0) -> (31.9569, 2.5)
  line L3 (144.9569, 0) -> (31.9569, 0)
  line L4 (144.9569, 2.5) -> (144.9569, 0)
  line L5 (137.9569, 0) -> (144.9569, 0)
  line L6 (137.9569, 0) -> (144.9569, 0)
  line L7 (137.9569, 2.5) -> (137.9569, 0)
  line L8 (144.9569, 2.5) -> (137.9569, 2.5)
  line L9 (144.9569, 0) -> (144.9569, 2.5)
  line L10 (114.9569, 0) -> (137.9569, 0)
  line L11 (114.9569, 2.5) -> (114.9569, 0)
  line L12 (137.9569, 2.5) -> (114.9569, 2.5)
  line L13 (137.9569, 0) -> (137.9569, 2.5)
  line L14 (107.9569, 2.5) -> (114.9569, 2.5)
  line L15 (107.9569, -2.5) -> (107.9569, 2.5)
  line L16 (114.9569, -2.5) -> (107.9569, -2.5)
  line L17 (114.9569, 2.5) -> (114.9569, -2.5)
  line L18 (64.9569, 0) -> (107.9569, 0)
  line L19 (64.9569, 2.5) -> (64.9569, 0)
  line L20 (107.9569, 2.5) -> (64.9569, 2.5)
  line L21 (107.9569, 0) -> (107.9569, 2.5)
  line L22 (57.9569, 2.5) -> (64.9569, 2.5)
  line L23 (57.9569, -2.5) -> (57.9569, 2.5)
  line L24 (64.9569, -2.5) -> (57.9569, -2.5)
  line L25 (64.9569, 2.5) -> (64.9569, -2.5)
  line L26 (31.9569, 0) -> (57.9569, 0)
  line L27 (31.9569, 2.5) -> (31.9569, 0)
  line L28 (57.9569, 2.5) -> (31.9569, 2.5)
  line L29 (57.9569, 0) -> (57.9569, 2.5)
  line L30 (51.9569, 2.5) -> (31.9569, 2.5)
  line L31 (137.9569, 2.5) -> (137.9569, 0)
  line L32 (52, 0) -> (51.9569, 2.5)
  curve K1 (-92.5167, 2.5) -> (22.9325, 2.5)
  curve K2 (-92.5167, 12.5) -> (-92.5167, 2.5)
  curve K3 (22.9325, 12.5) -> (-92.5167, 12.5)
  curve K4 (22.9325, 2.5) -> (22.9325, 12.5)
  line L33 (24.7487, 2.5) -> (0, 2.5)
  curve K5 (82.2982, -2) -> (35.3011, -2)
  curve K6 (82.2982, 8) -> (82.2982, -2)
  curve K7 (35.3011, 8) -> (82.2982, 8)
  curve K8 (35.3011, -2) -> (35.3011, 8)
  curve K9 (87.4118, 3) -> (1.7136, 3)
  curve K10 (87.4118, 13) -> (87.4118, 3)
  curve K11 (1.7136, 13) -> (87.4118, 13)
  curve K12 (1.7136, 3) -> (1.7136, 13)
  point P5 (144.9569, 0)
  point P6 (144.9569, 0)
  point P9 (137.9569, 2.5)
  point P19 (64.9569, 2.5)
  point P17 (107.9569, 0)
  point P3 (31.9569, 2.5)
  point P26 (31.9569, 2.5)
  point P24 (57.9569, 0)
  point P28 (31.9569, 2.5)
  point P30 (52, 0)
  point P31 (22.9325, 2.5)
  point P41 (1.7136, 3)
  point P45 (1.7136, 3)
  point P7 (137.9569, 0)
  point P11 (114.9569, 0)
  point P12 (114.9569, 2.5)
  point P14 (107.9569, 2.5)
  point P16 (114.9569, -2.5)
  point P18 (64.9569, 0)
  point P21 (57.9569, 2.5)
  point P23 (64.9569, -2.5)
  point P29 (51.9569, 2.5)
  coincident P5 P6
  perpendicular L4 L5
  horizontal L6
  vertical L7
  horizontal L8
  vertical L9
  coincident L1 P9
  horizontal L10
  vertical L11
  horizontal L12
  vertical L13
  horizontal L14
  vertical L15
  horizontal L16
  vertical L17
  horizontal L18
  vertical L19
  horizontal L20
  vertical L21
  coincident L1 P19
  midpoint L15 P17
  horizontal L22
  vertical L23
  horizontal L24
  vertical L25
  horizontal L26
  vertical L27
  horizontal L28
  vertical L29
  coincident P3 P26
  midpoint L23 P24
  coincident P3 P28
  perpendicular L27 L30
  coincident L26 P30
  perpendicular K1 K2
  parallel K1 K3
  parallel K2 K4
  coincident P31 L33
  perpendicular K5 K6
  parallel K5 K7
  parallel K6 K8
  perpendicular K9 K10
  parallel K9 K11
  parallel K10 K12
  coincident P41 P45
  dimension "d39" distance P6 P7 = 7
  dimension "d40" distance P7 P11 = 23
  dimension "d41" distance P12 P14 = 7
  dimension "d42" distance P12 P16 = 5
  dimension "d43" distance P17 P18 = 43
  dimension "d44" distance P19 P21 = 7
  dimension "d45" distance P19 P23 = 5
  dimension "d46" distance P28 P29 = 20
split_face "SplitFace1"
split_face "SplitFace2"
extrude "Extrude6" cut of existing geometry blind -1
extrude "Extrude7" cut sketch "Sketch9" profile of L1 L3 L23 L26 L28 L29 L32 against normal blind 1
extrude "Extrude8" cut sketch "Sketch9" profile of L1 L3 L15 L18 L19 L20 L21 L25 against normal blind 1
extrude "Extrude9" cut sketch "Sketch9" profile of L1 L3 L7 L10 L11 L12 L13 L17 L31 against normal blind 1
extrude "Extrude10" add of existing geometry blind 2
extrude "Extrude11" add of existing geometry blind 2
extrude "Extrude12" new body of existing geometry blind 7
fillet "Fillet4" radius 2
split "Split2"
component_from_bodies "Body->Comp"
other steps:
base_feature "Base Feature"
create_component "CreateComponent1"
remove_body "RemoveBody2"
